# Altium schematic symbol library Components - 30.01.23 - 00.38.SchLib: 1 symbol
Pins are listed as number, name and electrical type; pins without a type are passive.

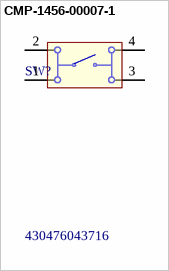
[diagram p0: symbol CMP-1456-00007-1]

## CMP-1456-00007-1
designator SW?, comment 430476043716
WS-TATV THT Tact Switch 12X12 mm; Manufacturer: Wuerth Elektronik; NoPins: 04
footprint 430476043716 (12*12mm vertical type,THT,  height 4.3mm, white actuator, 160gf, Bulk)
pins: 1, 2, 3, 4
